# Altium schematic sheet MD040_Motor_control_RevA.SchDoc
size 431 x 279 mm; Date: Not shown in title block; ApprovedBy: Not shown in title block; CheckedBy: Not shown in title block; Author: Not shown in title block; CompanyName: Not shown in title block; DrawnBy: ak; Engineer: Not shown in title block; Organization: Not shown in title block; Address1: Not shown in title block; Address2: Not shown in title block; Address3: Not shown in title block; Address4: Not shown in title block; DocumentNumber: 2; Revision: Use project parameter SCH_Rev; SheetNumber: 3; SheetTotal: 2; PageSetup: Record=PageOptions¦CenterHorizontal=True¦CenterVertical=True¦PrintScale=1.00¦XCorrection=1.00¦YCorrection=1.00¦PrintKind=0¦BorderSize=5000000¦LeftOffset=0¦BottomOffset=0¦Orientation=2¦PaperLength=1000¦PaperWidth=1000¦Scale=100¦PaperSource=15¦PrintQuality=600¦MediaType=1¦DitherType=10¦PaperKind=Letter¦PrintScaleMode=1
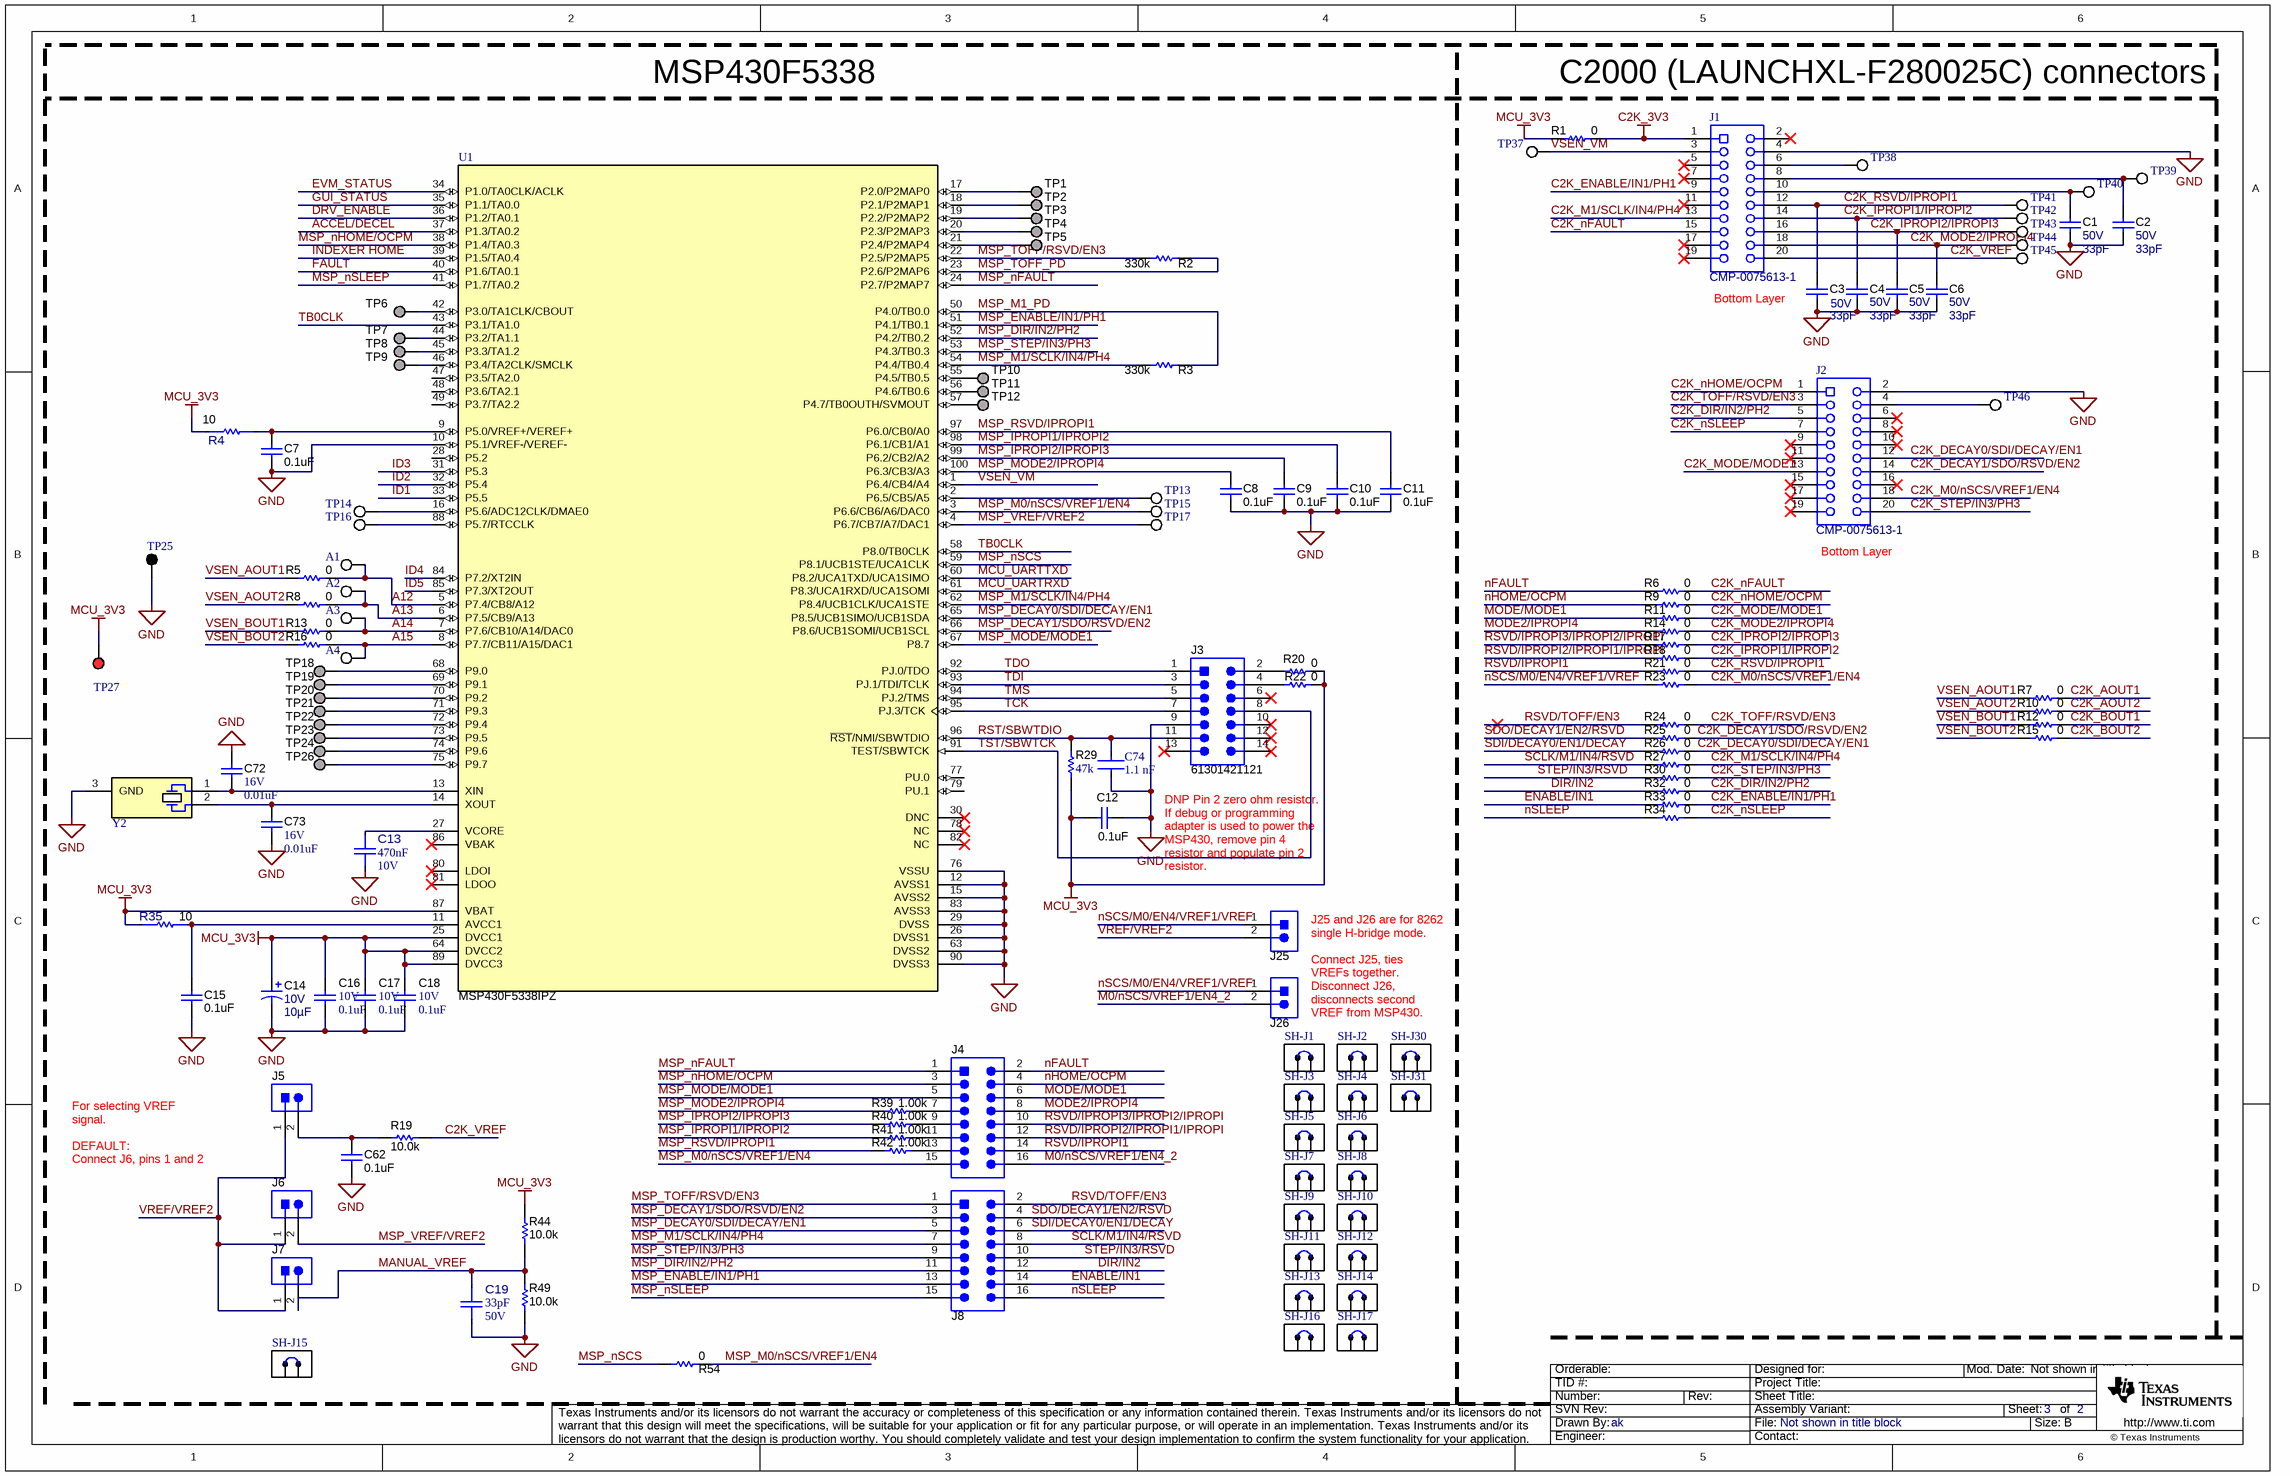
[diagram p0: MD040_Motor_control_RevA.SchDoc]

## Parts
A1  5012  [Keystone5012]  (value not drawn)
A2  5012  [Keystone5012]  (value not drawn)
A3  5012  [Keystone5012]  (value not drawn)
A4  5012  [Keystone5012]  (value not drawn)
C1  VDC_V: 50V  ValueDisplayed: 33pF  [0402]  (hidden comment: C1005C0G1H330J050BA)
C2  VDC_V: 50V  ValueDisplayed: 33pF  [0402]  (hidden comment: C1005C0G1H330J050BA)
C3  VDC_V: 50V  ValueDisplayed: 33pF  [0402]  (hidden comment: C1005C0G1H330J050BA)
C4  VDC_V: 50V  ValueDisplayed: 33pF  [0402]  (hidden comment: C1005C0G1H330J050BA)
C5  VDC_V: 50V  ValueDisplayed: 33pF  [0402]  (hidden comment: C1005C0G1H330J050BA)
C6  VDC_V: 50V  ValueDisplayed: 33pF  [0402]  (hidden comment: C1005C0G1H330J050BA)
C7  ValueDisplayed: 0.1uF  [0402L]  (hidden comment: 885012105010)
C8  ValueDisplayed: 0.1uF  [0402L]  (hidden comment: 885012105010)
C9  ValueDisplayed: 0.1uF  [0402L]  (hidden comment: 885012105010)
C10  ValueDisplayed: 0.1uF  [0402L]  (hidden comment: 885012105010)
C11  ValueDisplayed: 0.1uF  [0402L]  (hidden comment: 885012105010)
C12  ValueDisplayed: 0.1uF  [0402L]  (hidden comment: 885012105010)
C13  ValueDisplayed: 470nF  VDC_V: 10V  [FP-885012106008_0603-MFG]  (hidden comment: 885012106008)
C14  VDC_V: 10V  ValueDisplayed: 10µF  [3216-18]  (hidden comment: T520A106M010ATE080)
C15  ValueDisplayed: 0.1uF  [0402L]  (hidden comment: 885012105010)
C16  VDC_V: 10V  ValueDisplayed: 0.1uF  [0402]  (hidden comment: 885012105010)
C17  VDC_V: 10V  ValueDisplayed: 0.1uF  [0402]  (hidden comment: 885012105010)
C18  VDC_V: 10V  ValueDisplayed: 0.1uF  [0402]  (hidden comment: 885012105010)
C19  ValueDisplayed: 33pF  VDC_V: 50V  [FP-885012005058_0402-MFG]  (hidden comment: 885012005058)
C62  ValueDisplayed: 0.1uF  [0402L]  (hidden comment: 885012105010)
C72  VDC_V: 16V  ValueDisplayed: 0.01uF  [0402]  (hidden comment: 885012205031)
C73  VDC_V: 16V  ValueDisplayed: 0.01uF  [0402]  (hidden comment: 885012205031)
C74  1.1 nF  [FP-C0805C-DN-MFG]
J1  CMP-0075613-1  [Samtec_SSQ-110-03-x-D]
J2  CMP-0075613-1  [Samtec_SSQ-110-03-x-D]
J3  61301421121  [Wurth_61301421121]
J4  TSM-108-01-L-DV  [Samtec_TSM-108-01-x-DV]  (value not drawn)
J5  PBC02SAAN  [Sullins_PBC02SAAN]  (value not drawn)
J6  PBC02SAAN  [Sullins_PBC02SAAN]  (value not drawn)
J7  PBC02SAAN  [Sullins_PBC02SAAN]  (value not drawn)
J8  TSM-108-01-L-DV  [Samtec_TSM-108-01-x-DV]  (value not drawn)
J25  PBC02SAAN  [Sullins_PBC02SAAN]  (value not drawn)
J26  PBC02SAAN  [Sullins_PBC02SAAN]  (value not drawn)
R1  value 0  [0402L]  (hidden comment: Resistor)
R2  ValueDisplayed: 330k  [0603L]  (hidden comment: CRCW0603330KJNEA)
R3  ValueDisplayed: 330k  [0603L]  (hidden comment: CRCW0603330KJNEA)
R4  Res_ohm: 10  [FP-CH0402-10RJFPT_0402-MFG]  (hidden comment: CH0402-10RJFPT)
R5  value 0  [0402L]  (hidden comment: Resistor)
R6  value 0  [0402L]  (hidden comment: Resistor)
R7  value 0  [0402L]  (hidden comment: Resistor)
R8  value 0  [0402L]  (hidden comment: Resistor)
R9  value 0  [0402L]  (hidden comment: Resistor)
R10  value 0  [0402L]  (hidden comment: Resistor)
R11  value 0  [0402L]  (hidden comment: Resistor)
R12  value 0  [0402L]  (hidden comment: Resistor)
R13  value 0  [0402L]  (hidden comment: Resistor)
R14  value 0  [0402L]  (hidden comment: Resistor)
R15  value 0  [0402L]  (hidden comment: Resistor)
R16  value 0  [0402L]  (hidden comment: Resistor)
R17  value 0  [0402L]  (hidden comment: Resistor)
R18  value 0  [0402L]  (hidden comment: Resistor)
R19  ValueDisplayed: 10.0k  [0603]  (hidden comment: CRCW060310K0FKEA)
R20  value 0  [0402L]  (hidden comment: Resistor)
R21  value 0  [0402L]  (hidden comment: Resistor)
R22  value 0  [0402L]  (hidden comment: Resistor)
R23  value 0  [0402L]  (hidden comment: Resistor)
R24  value 0  [0402L]  (hidden comment: Resistor)
R25  value 0  [0402L]  (hidden comment: Resistor)
R26  value 0  [0402L]  (hidden comment: Resistor)
R27  value 0  [0402L]  (hidden comment: Resistor)
R29  ValueDisplayed: 47k  [0402]  (hidden comment: CRCW040247K0JNED)
R30  value 0  [0402L]  (hidden comment: Resistor)
R32  value 0  [0402L]  (hidden comment: Resistor)
R33  value 0  [0402L]  (hidden comment: Resistor)
R34  value 0  [0402L]  (hidden comment: Resistor)
R35  Res_ohm: 10  [FP-CH0402-10RJFPT_0402-MFG]  (hidden comment: CH0402-10RJFPT)
R39  ValueDisplayed: 1.00k  [0402L]  (hidden comment: CRCW04021K00FKED)
R40  ValueDisplayed: 1.00k  [0402L]  (hidden comment: CRCW04021K00FKED)
R41  ValueDisplayed: 1.00k  [0402L]  (hidden comment: CRCW04021K00FKED)
R42  ValueDisplayed: 1.00k  [0402L]  (hidden comment: CRCW04021K00FKED)
R44  ValueDisplayed: 10.0k  [0603]  (hidden comment: CRCW060310K0FKEA)
R49  ValueDisplayed: 10.0k  [0603]  (hidden comment: CRCW060310K0FKEA)
R54  value 0  [0402L]  (hidden comment: Resistor)
SH-J1  60900213421  [Wurth_60900213421]  (value not drawn)
SH-J2  60900213421  [Wurth_60900213421]  (value not drawn)
SH-J3  60900213421  [Wurth_60900213421]  (value not drawn)
SH-J4  60900213421  [Wurth_60900213421]  (value not drawn)
SH-J5  60900213421  [Wurth_60900213421]  (value not drawn)
SH-J6  60900213421  [Wurth_60900213421]  (value not drawn)
SH-J7  60900213421  [Wurth_60900213421]  (value not drawn)
SH-J8  60900213421  [Wurth_60900213421]  (value not drawn)
SH-J9  60900213421  [Wurth_60900213421]  (value not drawn)
SH-J10  60900213421  [Wurth_60900213421]  (value not drawn)
SH-J11  60900213421  [Wurth_60900213421]  (value not drawn)
SH-J12  60900213421  [Wurth_60900213421]  (value not drawn)
SH-J13  60900213421  [Wurth_60900213421]  (value not drawn)
SH-J14  60900213421  [Wurth_60900213421]  (value not drawn)
SH-J15  60900213421  [Wurth_60900213421]  (value not drawn)
SH-J16  60900213421  [Wurth_60900213421]  (value not drawn)
SH-J17  60900213421  [Wurth_60900213421]  (value not drawn)
SH-J30  60900213421  [Wurth_60900213421]  (value not drawn)
SH-J31  60900213421  [Wurth_60900213421]  (value not drawn)
TP1  TP_H0.45P0.75  [TP_H045P075]  (value not drawn)  (no BOM)
TP2  TP_H0.45P0.75  [TP_H045P075]  (value not drawn)  (no BOM)
TP3  TP_H0.45P0.75  [TP_H045P075]  (value not drawn)  (no BOM)
TP4  TP_H0.45P0.75  [TP_H045P075]  (value not drawn)  (no BOM)
TP5  TP_H0.45P0.75  [TP_H045P075]  (value not drawn)  (no BOM)
TP6  TP_H0.45P0.75  [TP_H045P075]  (value not drawn)  (no BOM)
TP7  TP_H0.45P0.75  [TP_H045P075]  (value not drawn)  (no BOM)
TP8  TP_H0.45P0.75  [TP_H045P075]  (value not drawn)  (no BOM)
TP9  TP_H0.45P0.75  [TP_H045P075]  (value not drawn)  (no BOM)
TP10  TP_H0.45P0.75  [TP_H045P075]  (value not drawn)  (no BOM)
TP11  TP_H0.45P0.75  [TP_H045P075]  (value not drawn)  (no BOM)
TP12  TP_H0.45P0.75  [TP_H045P075]  (value not drawn)  (no BOM)
TP13  5012  [Keystone5012]  (value not drawn)
TP14  5012  [Keystone5012]  (value not drawn)
TP15  5012  [Keystone5012]  (value not drawn)
TP16  5012  [Keystone5012]  (value not drawn)
TP17  5012  [Keystone5012]  (value not drawn)
TP18  TP_H0.45P0.75  [TP_H045P075]  (value not drawn)  (no BOM)
TP19  TP_H0.45P0.75  [TP_H045P075]  (value not drawn)  (no BOM)
TP20  TP_H0.45P0.75  [TP_H045P075]  (value not drawn)  (no BOM)
TP21  TP_H0.45P0.75  [TP_H045P075]  (value not drawn)  (no BOM)
TP22  TP_H0.45P0.75  [TP_H045P075]  (value not drawn)  (no BOM)
TP23  TP_H0.45P0.75  [TP_H045P075]  (value not drawn)  (no BOM)
TP24  TP_H0.45P0.75  [TP_H045P075]  (value not drawn)  (no BOM)
TP25  5011  [Keystone5011]  (value not drawn)
TP26  TP_H0.45P0.75  [TP_H045P075]  (value not drawn)  (no BOM)
TP27  5010  [Keystone5010]  (value not drawn)
TP37  5012  [Keystone5012]  (value not drawn)
TP38  5012  [Keystone5012]  (value not drawn)
TP39  5012  [Keystone5012]  (value not drawn)
TP40  5012  [Keystone5012]  (value not drawn)
TP41  5012  [Keystone5012]  (value not drawn)
TP42  5012  [Keystone5012]  (value not drawn)
TP43  5012  [Keystone5012]  (value not drawn)
TP44  5012  [Keystone5012]  (value not drawn)
TP45  5012  [Keystone5012]  (value not drawn)
TP46  5012  [Keystone5012]  (value not drawn)
U1  MSP430F5338IPZ  [PZT0100A_N]
Y2  MS3V-T1R 32.768KHZ +/-20PPM 12.5PF  [XTAL_MS3V-T1R]  (value not drawn)

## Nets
C2K_3V3: J1.1 R1.2
GND: C1.2 C2.2 C3.2 C4.2 C5.2 C6.2 C7.1 C8.1 C9.1 C10.1 C11.1 C12.2 C13.2 C14.2(-) C15.1 C16.2 C17.2 C18.2 C19.2 C62.1 C72.2 C73.1 C74.2 J1.4 J2.2 J3.9 R49.1 TP25.1 U1.10(P5.1/VREF-/VEREF-) U1.12(AVSS1) U1.15(AVSS2) U1.26(DVSS1) U1.29(DVSS) U1.63(DVSS2) U1.76(VSSU) U1.83(AVSS3) U1.90(DVSS3) Y2.3(GND)
MCU_3V3: C12.1 C14.1(+) C16.1 C17.1 C18.1 R1.1 R4.1 R20.2 R22.2 R29.1 R35.1 R44.2 TP27.1 U1.25(DVCC1) U1.64(DVCC2) U1.87(VBAT) U1.89(DVCC3)
A12: A1.1 R5.2 U1.5(P7.4/CB8/A12)
A13: A2.1 R8.2 U1.6(P7.5/CB9/A13)
A14: A3.1 R13.2 U1.7(P7.6/CB10/A14/DAC0)
A15: A4.1 R16.2 U1.8(P7.7/CB11/A15/DAC1)
ACCEL/DECEL: U1.37(P1.3/TA0.2)
C2K_AOUT1: R7.2
C2K_AOUT2: R10.2
C2K_BOUT1: R12.2
C2K_BOUT2: R15.2
C2K_DECAY0/SDI/DECAY/EN1: J2.12 R26.2
C2K_DECAY1/SDO/RSVD/EN2: J2.14 R25.2
C2K_DIR/IN2/PH2: J2.5 R32.2
C2K_ENABLE/IN1/PH1: J1.9 R33.2
C2K_IPROPI1/IPROPI2: C4.1 J1.14 R18.2 TP42.1
C2K_IPROPI2/IPROPI3: C5.1 J1.16 R17.2 TP43.1
C2K_M0/nSCS/VREF1/EN4: J2.18 R23.2
C2K_M1/SCLK/IN4/PH4: J1.13 R27.2
C2K_MODE2/IPROPI4: C6.1 J1.18 R14.2 TP44.1
C2K_MODE/MODE1: J2.13 R11.2
C2K_nFAULT: J1.15 R6.2
C2K_nHOME/OCPM: J2.1 R9.2
C2K_nSLEEP: J2.7 R34.2
C2K_RSVD/IPROPI1: C3.1 J1.12 R21.2 TP41.1
C2K_STEP/IN3/PH3: J2.20 R30.2
C2K_TOFF/RSVD/EN3: J2.3 R24.2
C2K_VREF: J1.20 R19.1 TP45.1
DIR/IN2: J8.12 R32.1
DRV_ENABLE: U1.36(P1.2/TA0.1)
ENABLE/IN1: J8.14 R33.1
EVM_STATUS: U1.34(P1.0/TA0CLK/ACLK)
FAULT: U1.40(P1.6/TA0.1)
GUI_STATUS: U1.35(P1.1/TA0.0)
ID1: U1.33(P5.5)
ID2: U1.32(P5.4)
ID3: U1.31(P5.3)
ID4: U1.84(P7.2/XT2IN)
ID5: U1.85(P7.3/XT2OUT)
INDEXER HOME: U1.39(P1.5/TA0.4)
M0/nSCS/VREF1/EN4_2: J4.16 J26.2
MANUAL_VREF: C19.1 J7.2 R44.1 R49.2
MCU_UARTRXD: U1.61(P8.3/UCA1RXD/UCA1SOMI)
MCU_UARTTXD: U1.60(P8.2/UCA1TXD/UCA1SIMO)
MODE2/IPROPI4: J4.8 R14.1
MODE/MODE1: J4.6 R11.1
MSP_DECAY0/SDI/DECAY/EN1: J8.5 U1.65(P8.5/UCB1SIMO/UCB1SDA)
MSP_DECAY1/SDO/RSVD/EN2: J8.3 U1.66(P8.6/UCB1SOMI/UCB1SCL)
MSP_DIR/IN2/PH2: J8.11 U1.52(P4.2/TB0.2)
MSP_ENABLE/IN1/PH1: J8.13 U1.51(P4.1/TB0.1)
MSP_IPROPI1/IPROPI2: C10.2 R41.1 U1.98(P6.1/CB1/A1)
MSP_IPROPI2/IPROPI3: C9.2 R40.1 U1.99(P6.2/CB2/A2)
MSP_M0/nSCS/VREF1/EN4: J4.15 R54.2 TP15.1 U1.3(P6.6/CB6/A6/DAC0)
MSP_M1/SCLK/IN4/PH4: J8.7 R3.1 U1.54(P4.4/TB0.4) U1.62(P8.4/UCB1CLK/UCA1STE)
MSP_M1_PD: R3.2 U1.50(P4.0/TB0.0)
MSP_MODE2/IPROPI4: C8.2 R39.1 U1.100(P6.3/CB3/A3)
MSP_MODE/MODE1: J4.5 U1.67(P8.7)
MSP_nFAULT: J4.1 U1.24(P2.7/P2MAP7)
MSP_nHOME/OCPM: J4.3 U1.38(P1.4/TA0.3)
MSP_nSCS: R54.1 U1.59(P8.1/UCB1STE/UCA1CLK)
MSP_nSLEEP: J8.15 U1.41(P1.7/TA0.2)
MSP_RSVD/IPROPI1: C11.2 R42.1 U1.97(P6.0/CB0/A0)
MSP_STEP/IN3/PH3: J8.9 U1.53(P4.3/TB0.3)
MSP_TOFF/RSVD/EN3: J8.1 R2.1 U1.22(P2.5/P2MAP5)
MSP_TOFF_PD: R2.2 U1.23(P2.6/P2MAP6)
MSP_VREF/VREF2: J6.2 TP17.1 U1.4(P6.7/CB7/A7/DAC1)
nFAULT: J4.2 R6.1
nHOME/OCPM: J4.4 R9.1
nSCS/M0/EN4/VREF1/VREF: J25.1 J26.1 R23.1
nSLEEP: J8.16 R34.1
RST/SBWTDIO: C74.1 J3.11 R29.2 U1.96(~{RST}/NMI/SBWTDIO)
RSVD/IPROPI1: J4.14 R21.1
RSVD/IPROPI2/IPROPI1/IPROPI: J4.12 R18.1
RSVD/IPROPI3/IPROPI2/IPROPI: J4.10 R17.1
RSVD/TOFF/EN3: J8.2 R24.1
SCLK/M1/IN4/RSVD: J8.8 R27.1
SDI/DECAY0/EN1/DECAY: J8.6 R26.1
SDO/DECAY1/EN2/RSVD: J8.4 R25.1
STEP/IN3/RSVD: J8.10 R30.1
TB0CLK: U1.43(P3.1/TA1.0) U1.58(P8.0/TB0CLK)
TCK: J3.7 U1.95(PJ.3/TCK)
TDI: J3.3 U1.93(PJ.1/TDI/TCLK)
TDO: J3.1 U1.92(PJ.0/TDO)
TMS: J3.5 U1.94(PJ.2/TMS)
TST/SBWTCK: J3.8 U1.91(TEST/SBWTCK)
VREF/VREF2: J5.1 J6.1 J7.1 J25.2
VSEN_AOUT1: R5.1 R7.1
VSEN_AOUT2: R8.1 R10.1
VSEN_BOUT1: R12.1 R13.1
VSEN_BOUT2: R15.1 R16.1
VSEN_VM: J1.3 TP37.1 U1.1(P6.4/CB4/A4)
NetC1_1: C1.1 J1.10 TP40.1
NetC2_1: C2.1 J1.8 TP39.1
NetC7_2: C7.2 R4.2 U1.9(P5.0/VREF+/VEREF+)
NetC13_1: C13.1 U1.27(VCORE)
NetC15_2: C15.2 R35.2 U1.11(AVCC1)
NetC62_2: C62.2 J5.2 R19.2
NetC72_1: C72.1 U1.13(XIN) Y2.1
NetC73_2: C73.2 U1.14(XOUT) Y2.2
NetJ1_6: J1.6 TP38.1
NetJ2_4: J2.4 TP46.1
NetJ3_2: J3.2 R20.1
NetJ3_4: J3.4 R22.1
NetJ4_7: J4.7 R39.2
NetJ4_9: J4.9 R40.2
NetJ4_11: J4.11 R41.2
NetJ4_13: J4.13 R42.2
NetTP1_1: TP1.1 U1.17(P2.0/P2MAP0)
NetTP2_1: TP2.1 U1.18(P2.1/P2MAP1)
NetTP3_1: TP3.1 U1.19(P2.2/P2MAP2)
NetTP4_1: TP4.1 U1.20(P2.3/P2MAP3)
NetTP5_1: TP5.1 U1.21(P2.4/P2MAP4)
NetTP6_1: TP6.1 U1.42(P3.0/TA1CLK/CBOUT)
NetTP7_1: TP7.1 U1.44(P3.2/TA1.1)
NetTP8_1: TP8.1 U1.45(P3.3/TA1.2)
NetTP9_1: TP9.1 U1.46(P3.4/TA2CLK/SMCLK)
NetTP10_1: TP10.1 U1.55(P4.5/TB0.5)
NetTP11_1: TP11.1 U1.56(P4.6/TB0.6)
NetTP12_1: TP12.1 U1.57(P4.7/TB0OUTH/SVMOUT)
NetTP13_1: TP13.1 U1.2(P6.5/CB5/A5)
NetTP14_1: TP14.1 U1.16(P5.6/ADC12CLK/DMAE0)
NetTP16_1: TP16.1 U1.88(P5.7/RTCCLK)
NetTP18_1: TP18.1 U1.68(P9.0)
NetTP19_1: TP19.1 U1.69(P9.1)
NetTP20_1: TP20.1 U1.70(P9.2)
NetTP21_1: TP21.1 U1.71(P9.3)
NetTP22_1: TP22.1 U1.72(P9.4)
NetTP23_1: TP23.1 U1.73(P9.5)
NetTP24_1: TP24.1 U1.74(P9.6)
NetTP26_1: TP26.1 U1.75(P9.7)

Not connected (* = marked no-connect by the designer): J1 2* 5* 7* 11* 17* 19*; J2 6* 8* 9* 10* 11* 15* 16* 17* 19*; J3 6* 10* 12* 13* 14*; U1 28(P5.2) 30(DNC)* 47(P3.5/TA2.0) 48(P3.6/TA2.1) 49(P3.7/TA2.2) 77(PU.0) 78(NC)* 79(PU.1) 80(LDOI)* 81(LDOO)* 82(NC)* 86(VBAK)*

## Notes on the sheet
- MSP430F5338
- C2000 (LAUNCHXL-F280025C) connectors
- Bottom Layer
- (near J2) Bottom Layer
- DNP Pin 2 zero ohm resistor. If debug or programming adapter is used to power the MSP430, remove pin 4 resistor and populate pin 2 resistor.
- J25 and J26 are for 8262 single H-bridge mode.
  Connect J25, ties VREFs together. Disconnect J26, disconnects second VREF from MSP430.
- For selecting VREF signal.
  DEFAULT:
  Connect J6, pins 1 and 2

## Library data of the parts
A1-A4 TP13-TP17 TP37-TP46 = CMP-0055149-1: Test Point, Multipurpose, White, TH; Manufacturer: Keystone; CNHeader: FALSE; Green_Lifecycle: Active; Green_REACh: Passed; ContactFinish: Silver; CT: TRUE
C1-C6 = CMP-0006250-2: CAP, CERM, 33 pF, 50 V, +/- 5%, C0G/NP0, 0402; Manufacturer: TDK; Alternate Manufacturer: Wurth Electronics; Alternate PartNumber: 885012005058; TaMin_C: -55°C; Polarized: N; SizeAreaWB_mm2: 3; Value1: Unknown; U/M: EA; Value: 33pF; TaMax_C: 125°C; SizeZ_mm: 0.6; SizeX_mm: 1; SizeY_mm: 0.5; AEC Category: Q200
C7-C12 C15 C62 = CMP-0006221-1: CAP, CERM, 0.1 uF, 10 V, +/- 20%, X5R, 0402; Manufacturer: Wurth Elektronik; Value: 0.1uF; Polarized: N; U/M: EA; Cap_F: 100nF; Value1: Unknown; VDC_V: 10V; TaMin_C: -55°C; TaMax_C: 85°C; Cap_Case: 0402; AEC Category: Q200; SizeArea_mm2: 0.5; SizeAreaWB_mm2: 3; SizeX_mm: 1; SizeZ_mm: 0.6
C13 = CMP-0097299-1: 0.47 µF ±20% 10V Ceramic Capacitor X5R 0603 (1608 Metric); Manufacturer: Wurth Electronics; Value: 470nF; AEC Qualified: No; TempCo: 15%; SizeZ_mm: 0.87mm
C14 = CMP-0084376-1: CAP, Tantalum Polymer, 10 µF, 10 V,+/- 20%, 0.08 ohm, 3216-18 SMD; Manufacturer: Kemet; TaMin_C: -55°C; SizeArea_mm2: 5.12; Value: 10uF; SizeAreaWB_mm2: 10.92; SizeY_mm: 1.6; Polarized: Y; SizeX_mm: 3.2; AEC Qualified: N; TaMax_C: 105°C; SizeZ_mm: 1.8; ESR_ohm: 0.08; CompType: Capacitor; AEC Category: Q200
C16-C18 = CMP-0006221-2: CAP, CERM, 0.1 uF, 10 V, +/- 20%, X5R, 0402; Manufacturer: Wurth Elektronik; TaMin_C: -55°C; Polarized: N; SizeAreaWB_mm2: 3; Value1: Unknown; U/M: EA; Value: 0.1uF; TaMax_C: 85°C; SizeZ_mm: 0.6; SizeX_mm: 1; SizeY_mm: 0.5; Cap_F: 100nF; AEC Category: Q200
C19 = CMP-0097306-1: 33 pF ±5% 50V Ceramic Capacitor C0G, NP0 0402 (1005 Metric); Manufacturer: Wurth Electronics; AEC Qualified: No; Value: 33pF; TempCo: 30ppm/°C; SizeZ_mm: 0.55mm
C72 C73 = CMP-0006227-2: CAP, CERM, 0.01 uF, 16 V, +/- 10%, X7R, 0402; Manufacturer: Wurth Elektronik; TaMin_C: -55°C; Polarized: N; SizeAreaWB_mm2: 3; Value1: Unknown; U/M: EA; Value: 0.01uF; TaMax_C: 125°C; SizeZ_mm: 0.6; SizeX_mm: 1; SizeY_mm: 0.5; Cap_F: 10nF; AEC Category: Q200
C74 = CMP-1036-03017-2: CAP CER 1100PF 50V NP0 0805; Manufacturer: KEMET; Manufacturer Part Number: C0805C112F5GACTU; PartNumber: C0805C112F5GAC7800; Value: 1,100 pF; Tolerance: 0.01; Material: Ceramic; Temperature Characteristic: C0G; Temperature Coefficient: 30ppm/°C
J1 J2 = CMP-0075613-1: Receptacle, 2.54mm, 10x2, Gold, TH; PartNumber: SSQ-110-03-G-D; Manufacturer: Samtec; CompType: Socket Strip; Pitch_mm: 2.54; Gender: Female; Row_Count: 2; Current_A: 6.3A; Voltage_V: 550V; Cert_CSA: Y; Cert_CULUS: N; CT: True; CNHeader: False
J3 = CMP-0086014-1: Header, 2.54mm, 7x2, Gold, TH; Manufacturer: Wurth Elektronik; Pitch_mm: 2.54; Voltage_V: 250V; Shrouded: N; Gender: Male; Current_A: 3A; Cert_UL: Y; Row_Count: 2
J4 J8 = CMP-0075595-1: Header, 2.54mm, 8x2, Gold, SMT; Manufacturer: Samtec; Pitch_mm: 2.54; Gender: Male; Cert_CSA: Y; Current_A: 4.9A; Voltage_V: 475V; CT: False; Shrouded: N; Row_Count: 2; CNHeader: True
J5-J7 J25 J26 = CMP-0054566-1: Header, 100mil, 2x1, Gold, TH; Manufacturer: Sullins Connector Solutions; Alternate Manufacturer: Wurth Electronics; Alternate PartNumber: 61300211121; CNHeader: TRUE; Current_A: 3A; Green_Lifecycle: Active; Shrouded: N; Gender: Male; Green_REACh: Passed; Voltage_V: 1.8kV; Row_Count: 1; Pitch_mm: 2.54; CT: FALSE; Cert_UL: Y
R1 R5-R18 R20-R27 R30 R32-R34 R54 = CMP-0026992-3: RES, 0, 5%, 0.1 W, AEC-Q200 Grade 0, 0402; Manufacturer: Panasonic; PartNumber: ERJ-2GE0R00X; Value_Code: 0000; Power_W: 100mW; Value2: 0.1W; VDC_V: 50V; TempCo: 600 ppm/C; EIA_Code: E24; AEC Category: Q200; AEC Qualified: Y; SizeArea_mm2: 0.5; SizeAreaWB_mm2: 3; SizeX_mm: 1; SizeZ_mm: 0.6
R2 R3 = CMP-0025784-3: RES, 330 k, 5%, 0.1 W, 0603; Manufacturer: Vishay-Dale; Power_W: 100mW; TempCo: 200 ppm/C; U/M: EA; Value: 330k; EIA_Code: E24; SizeX_mm: 1.6; SizeY_mm: 0.8; SizeZ_mm: 1; Value2: 0.1W; SizeArea_mm2: 1.28; VDC_V: 75V; AEC Category: Q200
R4 R35 = CMP-0091848-1: 10 Ohms ±5% 0.05W, 1/20W Chip Resistor 0402 (1005 Metric) RF, High Frequency Thin Film; Manufacturer: Vishay; SizeZ_mm: 0.627mm; VDC_V: 37V; TempCo: 100ppm/°C; Power_W: 50mW; AEC Qualified: No; Value: 10
R19 R44 R49 = CMP-0021998-3: RES, 10.0 k, 1%, 0.1 W, 0603; Manufacturer: Vishay-Dale; Power_W: 100mW; TempCo: 100 ppm/C; Value_Code: 10k0; U/M: EA; Value: 10.0k; EIA_Code: E96; Res_ohm: 10k; SizeX_mm: 1.6; SizeY_mm: 0.8; SizeZ_mm: 1; Value2: 0.1W; SizeArea_mm2: 1.28; VDC_V: 75V; AEC Category: Q200
R29 = CMP-0026935-3: RES, 47 k, 5%, 0.063 W, AEC-Q200 Grade 0, 0402; Manufacturer: Vishay-Dale; Power_W: 63mW; TempCo: 200 ppm/C; Value_Code: 47k0; Value: 47k; EIA_Code: E24; SizeX_mm: 1; SizeY_mm: 0.5; SizeZ_mm: 0.6; Value2: 0.063W; AEC Qualified: Y; VDC_V: 50V; AEC Category: Q200; AEC Grade: 0
R39-R42 = CMP-0026071-2: RES, 1.00 k, 1%, 0.063 W, 0402; Manufacturer: Vishay-Dale; Power_W: 63mW; TempCo: 100 ppm/C; Value_Code: 1k00; U/M: EA; Value: 1.00k; EIA_Code: E96; Res_ohm: 1k; SizeX_mm: 1; SizeY_mm: 0.5; SizeZ_mm: 0.6; Value2: 0.063W; VDC_V: 50V; AEC Category: Q200
SH-J1-SH-J17 SH-J30 SH-J31 = CMP-0003761-2: Shunt, 2.54mm, Gold, Black; Manufacturer: Wurth Elektronik
TP1-TP12 TP18-TP24 TP26 = CMP-0003719-1: Testpoint; Manufacturer: Texas Instruments; CompType: Pad
TP25 = CMP-0055148-1: Test Point, Multipurpose, Black, TH; Manufacturer: Keystone; CNHeader: FALSE; Green_Lifecycle: Active; Green_REACh: Passed; ContactFinish: Silver; CT: TRUE
TP27 = CMP-0055147-1: Test Point, Multipurpose, Red, TH; Manufacturer: Keystone; CNHeader: FALSE; Green_Lifecycle: Active; Green_REACh: Passed; ContactFinish: Silver; CT: TRUE
U1 = CMP-0038879-1: 20 MHz Mixed Signal Microcontroller with 256 KB Flash, 18432 B SRAM and 74 GPIOs, -40 to 85 degC, 100-pin QFP (PZ), Green (RoHS & no Sb/Br); Manufacturer: Texas Instruments; Flash(KB): 256; USCI_B (I2C & SPI): 2; ADC Channels: 16; Comparators: Yes; Frequency(MHz): 20; DMA: 3; SRAM(B): 18432; Multiplier: 32x32; GPIO: 74; Timers - 16-bit: 4; SubFamily: 5 Series; ADC: 12-bit SAR
Y2 = CMP-0004566-4: Crystal, 32.768 kHz, 12.5pF, SMD; Manufacturer: Micro Crystal AG; TaMin_C: -40°C; TaMax_C: 85°C; AEC Category: Q200; AEC Qualified: N; Frequency Tolerance: 20 ppm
